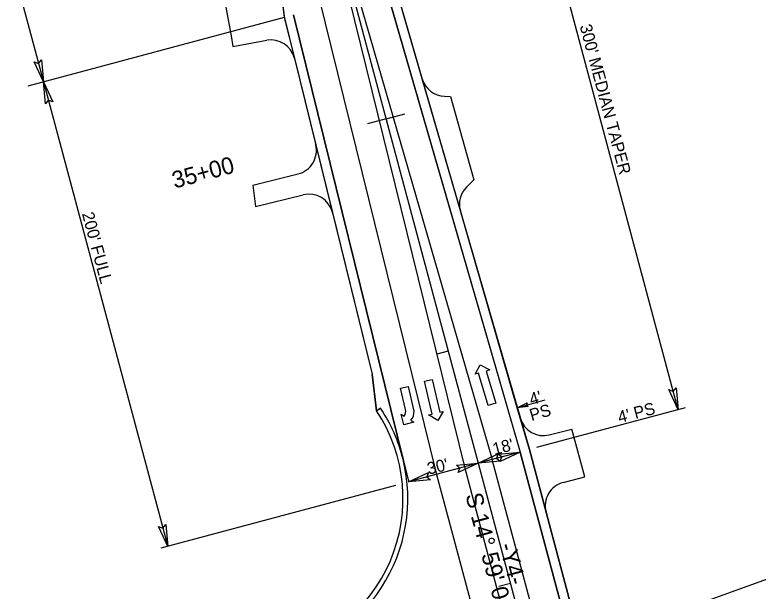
# Model space of a CAD drawing. Extents: x 1616561 to 1622460, y 896726 to 899651.
# Drawn here: x 1621262.4 to 1621571.6, y 898241.6 to 898481.3 of the extents above; entities that cross this region are included whole.
import ezdxf

# ---------------------------------------------------------------- set-up
doc = ezdxf.new("R2010")
doc.units = 0
for name, color, linetype in [('Old_Level_3', 7, 'Continuous'), ('Prop Dimension', 7, 'Continuous'), ('Prop Horizontal Alignment', 7, 'Continuous'), ('Prop Horizontal Alignment Tick Small', 7, 'Continuous'), ('Prop Lane Arrow CELL', 7, 'Continuous'), ('Prop Shade Light', 7, 'Continuous'), ('Prop Superelevation  Arrow CELL', 7, 'Continuous'), ('Prop Superelevation Label', 7, 'Continuous'), ('Prop Terminator CELL', 7, 'Continuous'), ('Scratch_Level_1', 7, 'Continuous'), ('Sheet Cutting Line CELL', 7, 'Continuous'), ('Sheet North Arrow CELL', 7, 'Continuous')]:
    doc.layers.add(name, color=color, linetype=linetype)

msp = doc.modelspace()

# ---------------------------------------------------------------- linework, layer by layer
at = {"layer": 'Old_Level_3'}
for p, q in [((1621377.59, 898584.62), (1621449.37, 898293.26)), ((1621377.59, 898584.62), (1621460.96, 898296.37)), ((1621365.94, 898581.75), (1621437.78, 898290.16)), ((1621423.89, 898296.37), (1621426.13, 898287.29)), ((1621498.38, 898156.58), (1621460.96, 898296.37)), ((1621449.37, 898293.27), (1621486.78, 898153.48)), ((1621437.78, 898290.17), (1621478.87, 898136.64))]:
    msp.add_line(p, q, dxfattribs=at)
at = {"layer": 'Prop Dimension'}
for p, q in [((1621538.31, 898317.08), (1621460.74, 898606.88)), ((1621248.4, 898550.03), (1621274.25, 898453.43)), ((1621374.47, 898480.26), (1621267.73, 898451.69)), ((1621274.25, 898453.43), (1621325.97, 898260.23)), ((1621471.4, 898317.84), (1621482.93, 898321.17)), ((1621541.21, 898317.86), (1621479.31, 898301.29)), ((1621472.55, 898299.48), (1621455.16, 898294.82)), ((1621455.16, 898294.81), (1621426.18, 898287.06)), ((1621420.67, 898285.58), (1621323.07, 898259.46))]:
    msp.add_line(p, q, dxfattribs=at)
at = {"layer": 'Prop Horizontal Alignment'}
for p, q in [((1621393.05, 898588.76), (1621476.41, 898300.51)), ((1621362.14, 898580.48), (1621374.4, 898480.55)), ((1621374.4, 898480.55), (1621411.04, 898331.8)), ((1621412.84, 898316.62), (1621411.04, 898331.8)), ((1621414.51, 898317.72), (1621412.84, 898316.62)), ((1621476.41, 898300.51), (1621513.83, 898160.72))]:
    msp.add_line(p, q, dxfattribs=at)
msp.add_arc((1621357.86, 898280.11), 68, 13.8393, 33.5864, dxfattribs=at)
at = {"layer": 'Prop Horizontal Alignment Tick Small'}
msp.add_line((1621414.51, 898317.72), (1621412.84, 898316.62), dxfattribs=at)
for radius, start in [(68, 13.8393), (66, 280.2581)]:
    msp.add_arc((1621357.86, 898280.11), radius, start, 33.5864, dxfattribs=at)
at = {"layer": 'Prop Lane Arrow CELL'}
for p, q in [((1621453.88, 898331.8), (1621455.96, 898335.7)), ((1621455.96, 898335.7), (1621459.92, 898333.59)), ((1621459.92, 898333.59), (1621458.48, 898333.16)), ((1621458.48, 898333.16), (1621462.45, 898319.74)), ((1621455.32, 898332.23), (1621453.88, 898331.8)), ((1621459.29, 898318.8), (1621455.32, 898332.23)), ((1621432.73, 898328.9), (1621435.94, 898329.66)), ((1621435.95, 898315.27), (1621432.73, 898328.9)), ((1621435.94, 898329.66), (1621439.16, 898316.03)), ((1621422.77, 898326.02), (1621425.98, 898326.78)), ((1621424.87, 898317.12), (1621422.77, 898326.02)), ((1621425.98, 898326.78), (1621428.41, 898316.52)), ((1621462.45, 898319.74), (1621459.29, 898318.8)), ((1621424.15, 898310.83), (1621423.07, 898315.2)), ((1621423.07, 898315.2), (1621424.33, 898314.42)), ((1621434.49, 898314.93), (1621435.95, 898315.27)), ((1621438.33, 898312.6), (1621434.49, 898314.93)), ((1621440.62, 898316.38), (1621438.33, 898312.6)), ((1621439.16, 898316.03), (1621440.62, 898316.38)), ((1621428.42, 898311.89), (1621424.15, 898310.83)), ((1621427.16, 898312.67), (1621428.42, 898311.89))]:
    msp.add_line(p, q, dxfattribs=at)
for centre, radius, start, end in [((1621421.71, 898316.36), 3.28, 323.647, 13.3051), ((1621423.19, 898316.09), 5.25, 319.3174, 4.6291)]:
    msp.add_arc(centre, radius, start, end, dxfattribs=at)
at = {"layer": 'Prop Shade Light'}
for p, q in [((1621423.89, 898296.37), (1621378.34, 898481.29)), ((1621471.4, 898317.84), (1621447.7, 898399.79)), ((1621411.04, 898331.8), (1621412.84, 898316.62)), ((1621476.41, 898300.51), (1621471.4, 898317.84)), ((1621412.84, 898316.62), (1621412.84, 898316.62)), ((1621472.55, 898299.48), (1621509.97, 898159.69)), ((1621513.83, 898160.72), (1621476.41, 898300.51))]:
    msp.add_line(p, q, dxfattribs=at)
for points in [[(1621389.18, 898587.72), (1621401.53, 898545.04), (1621472.55, 898299.48)], [(1621447.7, 898399.79), (1621431.82, 898454.69), (1621420.84, 898492.65), (1621397.02, 898575.03), (1621393.05, 898588.76)], [(1621362.14, 898580.48), (1621364.02, 898565.21), (1621367.63, 898535.83), (1621372.36, 898497.44), (1621374.47, 898480.26)], [(1621374.47, 898480.26), (1621378.66, 898463.25), (1621387.53, 898427.23), (1621394.45, 898399.15), (1621411.04, 898331.8)], [(1621412.84, 898316.62), (1621414.51, 898317.72), (1621414.51, 898317.72)], [(1621471.4, 898317.84), (1621471.4, 898317.84), (1621471.4, 898317.84)]]:
    msp.add_lwpolyline(points, dxfattribs=at)
msp.add_arc((1621357.86, 898280.11), 68, 13.8393, 33.5864, dxfattribs=at)
at = {"layer": 'Prop Superelevation  Arrow CELL'}
for p, q in [((1621442.69, 898341.42), (1621437.86, 898340.13)), ((1621468.55, 898244.82), (1621463.72, 898243.53))]:
    msp.add_line(p, q, dxfattribs=at)
at = {"layer": 'Prop Superelevation Label'}
for q in [(1621424.56, 898440.09), (1621409.11, 898435.95)]:
    msp.add_line((1621416.83, 898438.02), q, dxfattribs=at)
at = {"layer": 'Prop Terminator CELL'}
for p, q in [((1621389.18, 898587.72), (1621472.55, 898299.48)), ((1621350.19, 898484.54), (1621352.32, 898472.51)), ((1621378.34, 898481.29), (1621423.89, 898296.37)), ((1621352.32, 898472.51), (1621353, 898468.12)), ((1621353, 898468.12), (1621367.16, 898470.7)), ((1621441.11, 898447.47), (1621443.62, 898447.39)), ((1621443.62, 898447.39), (1621453.36, 898412.73)), ((1621361.43, 898410.5), (1621380.21, 898415.13)), ((1621361.43, 898410.5), (1621362.51, 898401.59)), ((1621450.27, 898409.68), (1621453.36, 898412.73)), ((1621362.51, 898401.59), (1621382.35, 898406.47)), ((1621484.71, 898306.61), (1621494.09, 898308.98)), ((1621499.5, 898289.2), (1621494.09, 898308.98)), ((1621509.97, 898159.69), (1621472.55, 898299.48)), ((1621490.49, 898286.85), (1621499.5, 898289.2))]:
    msp.add_line(p, q, dxfattribs=at)
for points in [[(1621273.42, 898462.53), (1621274.25, 898453.43), (1621270.37, 898461.76), (1621272.21, 898461.06)], [(1621275.08, 898444.34), (1621274.25, 898453.43), (1621278.14, 898445.1), (1621276.3, 898445.8)], [(1621537.48, 898326.17), (1621538.31, 898317.08), (1621534.43, 898325.41), (1621536.27, 898324.71)], [(1621475.94, 898318.35), (1621471.4, 898317.84), (1621475.53, 898319.87), (1621475.2, 898318.94)], [(1621463.46, 898298.65), (1621472.55, 898299.48), (1621464.22, 898295.59), (1621464.92, 898297.43)], [(1621464.26, 898295.65), (1621455.16, 898294.82), (1621463.49, 898298.71), (1621462.79, 898296.87)], [(1621446.07, 898293.99), (1621455.16, 898294.81), (1621446.84, 898290.93), (1621447.53, 898292.77)], [(1621435.28, 898287.89), (1621426.18, 898287.06), (1621434.51, 898290.94), (1621433.82, 898289.1)], [(1621325.14, 898269.33), (1621325.97, 898260.23), (1621322.08, 898268.56), (1621323.92, 898267.86)]]:
    msp.add_lwpolyline(points, close=True, dxfattribs=at)
for centre, radius, start, end in [((1621368.95, 898460.86), 10, 13.8393, 100.3157), ((1621441.43, 898457.47), 10, 196.1308, 268.1762), ((1621377.82, 898424.84), 10, 283.8392, 13.8393), ((1621457.31, 898402.57), 10, 134.7088, 196.1308), ((1621384.74, 898396.76), 10, 13.8393, 103.8392), ((1621482.26, 898316.31), 10, 196.1308, 284.1919), ((1621357.86, 898280.11), 68, 280.2581, 13.8393), ((1621493.01, 898277.17), 10, 104.6035, 194.9851)]:
    msp.add_arc(centre, radius, start, end, dxfattribs=at)
at = {"layer": 'Sheet Cutting Line CELL'}
msp.add_line((1621287.55, 898921.02), (1621727.49, 897277.4), dxfattribs=at)
at = {"layer": 'Sheet North Arrow CELL'}
msp.add_line((1621477.45, 898211.56), (1621735.86, 898304.31), dxfattribs=at)

# ---------------------------------------------------------------- texts
at = {"layer": 'Prop Dimension'}
for s, height, rotation, p in [("300' MEDIAN TAPER", 5, 284.985, (1621497.32, 898476.65)), ('35+00', 7, 14.985, (1621328.84, 898409.01)), ("200' FULL", 5, 284.985, (1621290.25, 898398.6)), ("4'", 5, 16.2142, (1621477.21, 898318.9)), ('PS', 5, 16.2142, (1621477.31, 898312.33)), ("4' PS", 5, 14.5706, (1621513.9, 898311.45)), ("18'", 5, 14.5706, (1621461.84, 898298.18)), ("30'", 5, 13.4181, (1621434.55, 898290.04))]:
    msp.add_text(s, height=height, rotation=rotation, dxfattribs=at).set_placement(p)
at = {"layer": 'Scratch_Level_1'}
for s, rotation, p in [('S 14%%d 59\' 06.0" E', 284.985, (1621449.74, 898281.5)), ('-Y4-', 284.9555, (1621463.77, 898260.74))]:
    msp.add_text(s, height=7, rotation=rotation, dxfattribs=at).set_placement(p)

doc.saveas('drawing.dxf')
